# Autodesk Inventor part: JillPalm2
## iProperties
Company: cbliss@cbliss.com
Author: Charles Bliss
Shininess: 0.0
PropertySet Name: _Private Model Information
Created: 2000-01
Part Number: JillPalm2
Project: Inventor Sample
Document SubType Name: Modeling
Designer: Charles Bliss
Control State: 0
Master: False
Checked Out: False
Density: 0.0
Volume: 0.0
Area: 0.0
PropertySet Name: Model Information
